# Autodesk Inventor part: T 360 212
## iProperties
Shininess: 64.0
Angle Display Precision: 2
Document Length Units: 11269
Document Angle Units: 11279
Document Time Units: 11290
Document Mass Units: 11283
Document Length Units Precision: 3
Document Angle Units Precision: 2
Compacted: True
Created: 2001-11
Part Number: T 360 212
Document SubType Name: Modeling
Designer: I.Baliuc
Material: 1.1200
Description: Druckfeder
Vendor: GUTERKUNST
Density: 7.84 g/cm^3
Density: 0.0
Volumn: 0.0
Area: 0.0
PropertySet Name: Model Information
Control State: 0
Master: False
Checked Out: False
HalbzeugNorm: VD-288S
Zweck: für Vorkontakt
Abmessung: 2.8 x 20.0 - 101
Author: T.Messerschmitt
Revision Number: 360212
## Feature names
1. Coil1
2. Extrusion1
3. Extrusion2
